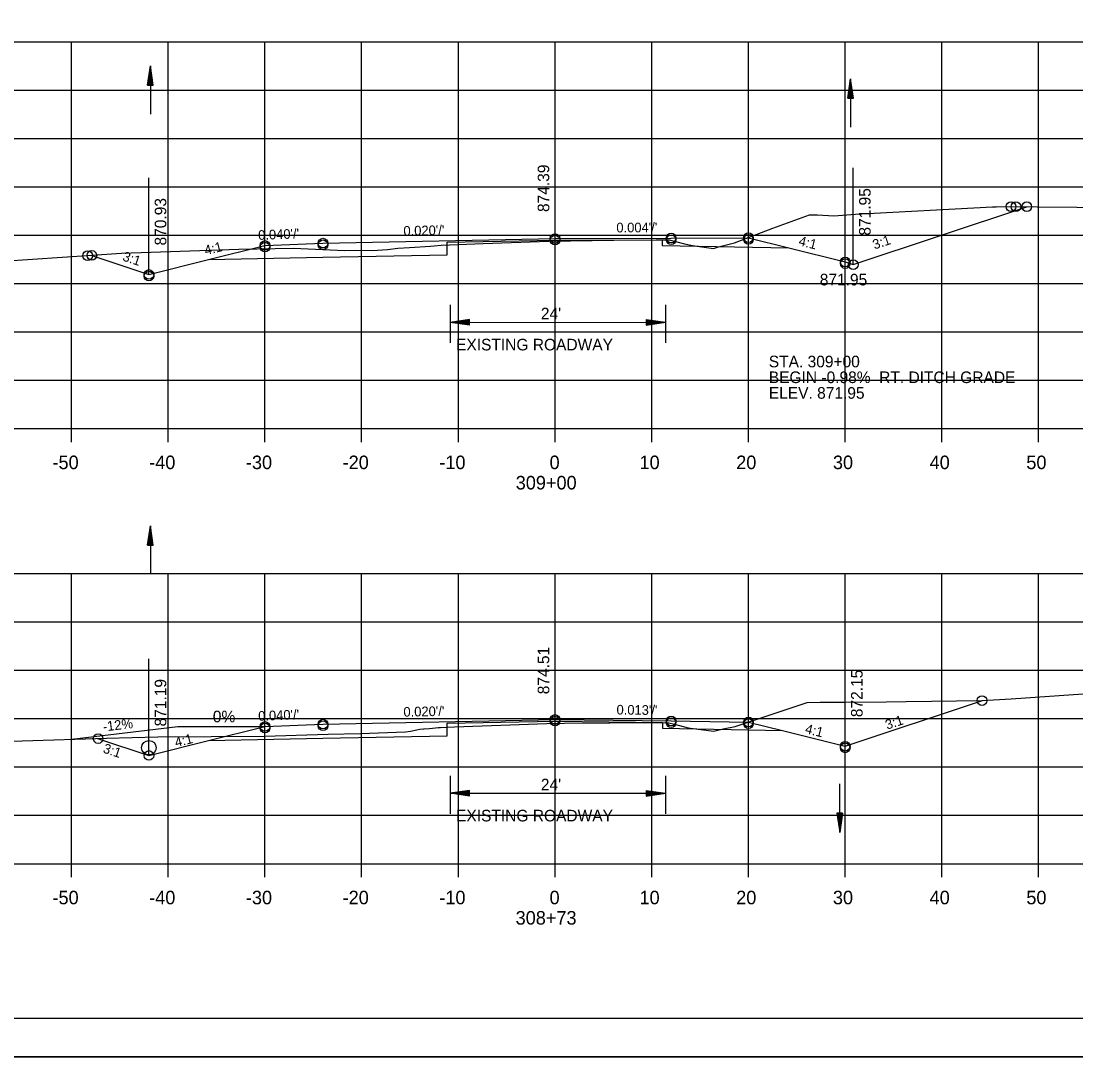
# Model space of a CAD drawing. Extents: x 1486524 to 1499135, y 326561 to 337924.
# Drawn here: x 1488927.7 to 1489036.7, y 334699.3 to 334806.5 of the extents above; entities that cross this region are included whole.
import ezdxf

# ---------------------------------------------------------------- set-up
doc = ezdxf.new("R2010")
doc.units = 0
for name, color, linetype in [('E_Const Align', 7, 'Continuous'), ('E_Const Align Station', 7, 'Continuous'), ('E_Ownership Information', 7, 'Continuous'), ('E_Property Line', 7, 'Continuous'), ('E_Proposed ROW and Easements', 7, 'Continuous'), ('E_Proposed ROW Fig Annot', 7, 'Continuous'), ('E_Quarter Calls', 7, 'Continuous'), ('E_Station Offset', 7, 'Continuous'), ('E_Survey Point', 7, 'Continuous'), ('E_Title Sheet', 7, 'Continuous'), ('E_Tract Number', 7, 'Continuous'), ('R_Water Annot', 7, 'Continuous'), ('R_Xsect Elev', 7, 'Continuous'), ('R_Xsect Slope', 7, 'Continuous')]:
    doc.layers.add(name, color=color, linetype=linetype)

msp = doc.modelspace()

# ---------------------------------------------------------------- linework, layer by layer
at = {"layer": 'E_Const Align'}
for p, q in [((1488842.89, 334764.33), (1489122.89, 334764.33)), ((1488932.89, 334762.93), (1488932.89, 334764.33)), ((1488942.89, 334762.93), (1488942.89, 334764.33)), ((1488952.89, 334762.93), (1488952.89, 334764.33)), ((1488962.89, 334762.93), (1488962.89, 334764.33)), ((1488972.89, 334762.93), (1488972.89, 334764.33)), ((1488982.89, 334762.93), (1488982.89, 334764.33)), ((1488992.89, 334762.93), (1488992.89, 334764.33)), ((1489002.89, 334762.93), (1489002.89, 334764.33)), ((1489012.89, 334762.93), (1489012.89, 334764.33)), ((1489022.89, 334762.93), (1489022.89, 334764.33)), ((1489032.89, 334762.93), (1489032.89, 334764.33)), ((1488842.89, 334719.33), (1489122.89, 334719.33)), ((1488932.89, 334717.93), (1488932.89, 334719.33)), ((1488942.89, 334717.93), (1488942.89, 334719.33)), ((1488952.89, 334717.93), (1488952.89, 334719.33)), ((1488962.89, 334717.93), (1488962.89, 334719.33)), ((1488972.89, 334717.93), (1488972.89, 334719.33)), ((1488982.89, 334717.93), (1488982.89, 334719.33)), ((1488992.89, 334717.93), (1488992.89, 334719.33)), ((1489002.89, 334717.93), (1489002.89, 334719.33)), ((1489012.89, 334717.93), (1489012.89, 334719.33)), ((1489022.89, 334717.93), (1489022.89, 334719.33)), ((1489032.89, 334717.93), (1489032.89, 334719.33))]:
    msp.add_line(p, q, dxfattribs=at)
at = {"layer": 'E_Ownership Information'}
for p, q in [((1488842.89, 334804.33), (1489122.89, 334804.33)), ((1488932.89, 334764.33), (1488932.89, 334804.33)), ((1488942.89, 334764.33), (1488942.89, 334804.33)), ((1488952.89, 334764.33), (1488952.89, 334804.33)), ((1488962.89, 334764.33), (1488962.89, 334804.33)), ((1488972.89, 334764.33), (1488972.89, 334804.33)), ((1488982.89, 334764.33), (1488982.89, 334804.33)), ((1488992.89, 334764.33), (1488992.89, 334804.33)), ((1489002.89, 334764.33), (1489002.89, 334804.33)), ((1489012.89, 334764.33), (1489012.89, 334804.33)), ((1489022.89, 334764.33), (1489022.89, 334804.33)), ((1489032.89, 334764.33), (1489032.89, 334804.33)), ((1488842.89, 334799.33), (1489122.89, 334799.33)), ((1488842.89, 334794.33), (1489122.89, 334794.33)), ((1488842.89, 334789.33), (1489122.89, 334789.33)), ((1488842.89, 334784.33), (1489122.89, 334784.33)), ((1488843.82, 334779.33), (1489123.82, 334779.33)), ((1488842.89, 334774.33), (1489122.89, 334774.33)), ((1488842.89, 334769.33), (1489122.89, 334769.33)), ((1488842.89, 334764.33), (1489122.89, 334764.33)), ((1488842.89, 334749.33), (1489122.89, 334749.33)), ((1488932.89, 334719.33), (1488932.89, 334749.33)), ((1488942.89, 334719.33), (1488942.89, 334749.33)), ((1488952.89, 334719.33), (1488952.89, 334749.33)), ((1488962.89, 334719.33), (1488962.89, 334749.33)), ((1488972.89, 334719.33), (1488972.89, 334749.33)), ((1488982.89, 334719.33), (1488982.89, 334749.33)), ((1488992.89, 334719.33), (1488992.89, 334749.33)), ((1489002.89, 334719.33), (1489002.89, 334749.33)), ((1489012.89, 334719.33), (1489012.89, 334749.33)), ((1489022.89, 334719.33), (1489022.89, 334749.33)), ((1489032.89, 334719.33), (1489032.89, 334749.33)), ((1488842.89, 334744.33), (1489122.89, 334744.33)), ((1488842.89, 334739.33), (1489122.89, 334739.33)), ((1488842.89, 334734.33), (1489122.89, 334734.33)), ((1488842.89, 334729.33), (1489122.89, 334729.33)), ((1488842.89, 334724.33), (1489122.89, 334724.33)), ((1488842.89, 334719.33), (1489122.89, 334719.33))]:
    msp.add_line(p, q, dxfattribs=at)
at = {"layer": 'E_Property Line'}
msp.add_line((1489141.07, 334703.33), (1488824.89, 334703.33), dxfattribs=at)
at = {"layer": 'E_Proposed ROW and Easements'}
for p, q in [((1488972.03, 334777.13), (1488972.03, 334773.2)), ((1488994.31, 334777.13), (1488994.31, 334773.2)), ((1488974.03, 334775.62), (1488972.03, 334775.31)), ((1488974.03, 334775.02), (1488972.03, 334775.31)), ((1488974.03, 334775.57), (1488972.37, 334775.31)), ((1488974.03, 334775.07), (1488972.37, 334775.31)), ((1488974.03, 334775.51), (1488972.71, 334775.31)), ((1488974.03, 334775.12), (1488972.71, 334775.31)), ((1488974.03, 334775.46), (1488973.04, 334775.31)), ((1488974.03, 334775.17), (1488973.04, 334775.31)), ((1488974.03, 334775.41), (1488973.38, 334775.31)), ((1488974.03, 334775.22), (1488973.38, 334775.31)), ((1488974.03, 334775.36), (1488973.72, 334775.31)), ((1488974.03, 334775.27), (1488973.72, 334775.31)), ((1488974.03, 334775.02), (1488974.03, 334775.62)), ((1488992.31, 334775.62), (1488994.31, 334775.32)), ((1488992.31, 334775.62), (1488992.31, 334775.02)), ((1488992.31, 334775.57), (1488993.97, 334775.32)), ((1488992.31, 334775.52), (1488993.63, 334775.32)), ((1488992.31, 334775.47), (1488993.3, 334775.32)), ((1488992.31, 334775.42), (1488992.96, 334775.32)), ((1488992.31, 334775.37), (1488992.62, 334775.32)), ((1488992.31, 334775.02), (1488994.31, 334775.32)), ((1488992.31, 334775.22), (1488992.96, 334775.32)), ((1488992.31, 334775.12), (1488993.63, 334775.32)), ((1488992.31, 334775.07), (1488993.97, 334775.32)), ((1488992.31, 334775.17), (1488993.3, 334775.32)), ((1488992.31, 334775.27), (1488992.62, 334775.32)), ((1488972.03, 334728.42), (1488972.03, 334724.5)), ((1488994.31, 334728.42), (1488994.31, 334724.5)), ((1488974.03, 334726.91), (1488972.03, 334726.61)), ((1488974.03, 334726.86), (1488972.37, 334726.61)), ((1488974.03, 334726.31), (1488974.03, 334726.91)), ((1488992.31, 334726.91), (1488994.31, 334726.61)), ((1488992.31, 334726.91), (1488992.31, 334726.31)), ((1488992.31, 334726.86), (1488993.97, 334726.61)), ((1488974.03, 334726.31), (1488972.03, 334726.61)), ((1488974.03, 334726.36), (1488972.37, 334726.61)), ((1488974.03, 334726.81), (1488972.71, 334726.61)), ((1488974.03, 334726.41), (1488972.71, 334726.61)), ((1488974.03, 334726.76), (1488973.04, 334726.61)), ((1488974.03, 334726.46), (1488973.04, 334726.61)), ((1488974.03, 334726.7), (1488973.38, 334726.61)), ((1488974.03, 334726.51), (1488973.38, 334726.61)), ((1488974.03, 334726.65), (1488973.72, 334726.61)), ((1488974.03, 334726.56), (1488973.72, 334726.61)), ((1488992.31, 334726.81), (1488993.63, 334726.61)), ((1488992.31, 334726.76), (1488993.3, 334726.61)), ((1488992.31, 334726.71), (1488992.96, 334726.61)), ((1488992.31, 334726.66), (1488992.62, 334726.61)), ((1488992.31, 334726.31), (1488994.31, 334726.61)), ((1488992.31, 334726.51), (1488992.96, 334726.61)), ((1488992.31, 334726.41), (1488993.63, 334726.61)), ((1488992.31, 334726.36), (1488993.97, 334726.61)), ((1488992.31, 334726.46), (1488993.3, 334726.61)), ((1488992.31, 334726.56), (1488992.62, 334726.61))]:
    msp.add_line(p, q, dxfattribs=at)
at = {"layer": 'E_Proposed ROW Fig Annot'}
for p, q in [((1488940.74, 334799.85), (1488941.04, 334801.85)), ((1488940.79, 334799.85), (1488941.04, 334801.51)), ((1488940.84, 334799.85), (1488941.04, 334801.17)), ((1488941.34, 334799.85), (1488941.04, 334801.85)), ((1488941.29, 334799.85), (1488941.04, 334801.51)), ((1488941.24, 334799.85), (1488941.04, 334801.17)), ((1488940.89, 334799.85), (1488941.04, 334800.84)), ((1488940.94, 334799.85), (1488941.04, 334800.5)), ((1488940.99, 334799.85), (1488941.04, 334800.16)), ((1488941.19, 334799.85), (1488941.04, 334800.84)), ((1488941.14, 334799.85), (1488941.04, 334800.5)), ((1488941.09, 334799.85), (1488941.04, 334800.16)), ((1489013.15, 334798.49), (1489013.45, 334800.49)), ((1489013.2, 334798.49), (1489013.45, 334800.16)), ((1489013.75, 334798.49), (1489013.45, 334800.49)), ((1489013.7, 334798.49), (1489013.45, 334800.16)), ((1488940.74, 334799.85), (1488941.34, 334799.85)), ((1489013.25, 334798.49), (1489013.45, 334799.82)), ((1489013.3, 334798.49), (1489013.45, 334799.48)), ((1489013.36, 334798.49), (1489013.45, 334799.14)), ((1489013.41, 334798.49), (1489013.45, 334798.81)), ((1489013.65, 334798.49), (1489013.45, 334799.82)), ((1489013.6, 334798.49), (1489013.45, 334799.48)), ((1489013.55, 334798.49), (1489013.45, 334799.14)), ((1489013.5, 334798.49), (1489013.45, 334798.81)), ((1489013.15, 334798.49), (1489013.75, 334798.49)), ((1488972.03, 334775.31), (1488994.31, 334775.32)), ((1488940.74, 334752.27), (1488941.04, 334754.27)), ((1488941.34, 334752.27), (1488941.04, 334754.27)), ((1488940.79, 334752.27), (1488941.04, 334753.93)), ((1488940.84, 334752.27), (1488941.04, 334753.59)), ((1488940.89, 334752.27), (1488941.04, 334753.25)), ((1488941.29, 334752.27), (1488941.04, 334753.93)), ((1488941.24, 334752.27), (1488941.04, 334753.59)), ((1488941.19, 334752.27), (1488941.04, 334753.25)), ((1488940.74, 334752.27), (1488941.34, 334752.27)), ((1488940.94, 334752.27), (1488941.04, 334752.92)), ((1488940.99, 334752.27), (1488941.04, 334752.58)), ((1488941.14, 334752.27), (1488941.04, 334752.92)), ((1488941.09, 334752.27), (1488941.04, 334752.58)), ((1488972.03, 334726.61), (1488994.31, 334726.61)), ((1489012.02, 334724.57), (1489012.32, 334722.57)), ((1489012.62, 334724.57), (1489012.02, 334724.57)), ((1489012.07, 334724.57), (1489012.32, 334722.9)), ((1489012.12, 334724.57), (1489012.32, 334723.25)), ((1489012.17, 334724.57), (1489012.32, 334723.58)), ((1489012.22, 334724.57), (1489012.32, 334723.92)), ((1489012.27, 334724.57), (1489012.32, 334724.25)), ((1489012.62, 334724.57), (1489012.32, 334722.57)), ((1489012.41, 334724.57), (1489012.32, 334723.92)), ((1489012.52, 334724.57), (1489012.32, 334723.25)), ((1489012.57, 334724.57), (1489012.32, 334722.9)), ((1489012.47, 334724.57), (1489012.32, 334723.58)), ((1489012.36, 334724.57), (1489012.32, 334724.25))]:
    msp.add_line(p, q, dxfattribs=at)
at = {"layer": 'E_Quarter Calls'}
msp.add_line((1488812.48, 334699.35), (1489145.82, 334699.35), dxfattribs=at)
for points in [[(1488812.48, 334912.69), (1489145.82, 334912.69), (1489145.82, 334699.35), (1488812.48, 334699.35)], [(1489058.81, 334908.79), (1489058.81, 334898.91), (1489094.54, 334898.91), (1489094.54, 334895.99), (1489117.74, 334895.99), (1489117.74, 334871.66), (1489141.07, 334871.66), (1489141.07, 334703.33), (1488824.89, 334703.33), (1488824.89, 334908.79)]]:
    msp.add_lwpolyline(points, close=True, dxfattribs=at)
for centre in [(1489030.04, 334787.28), (1489030.54, 334787.27), (1489031.67, 334787.27), (1488952.89, 334783.26), (1488952.89, 334783.26), (1488952.89, 334783.09), (1488958.89, 334783.5), (1488958.89, 334783.5), (1488958.89, 334783.33), (1488982.89, 334783.98), (1488982.89, 334783.98), (1488982.89, 334783.81), (1488994.89, 334784.03), (1488994.89, 334784.03), (1488994.89, 334783.86), (1489002.89, 334784.06), (1489002.89, 334784.06), (1489002.89, 334783.89), (1488934.56, 334782.2), (1488934.99, 334782.23), (1488934.99, 334782.23), (1489012.89, 334781.56), (1489012.89, 334781.56), (1489012.89, 334781.39), (1489013.72, 334781.28), (1488940.89, 334780.26), (1488940.89, 334780.26), (1488940.89, 334780.09), (1489027.04, 334736.2), (1489027.04, 334736.2), (1488982.89, 334734.24), (1488982.89, 334734.24), (1488982.89, 334734.07), (1488994.89, 334734.09), (1488994.89, 334734.09), (1489002.89, 334733.98), (1489002.89, 334733.98), (1488952.89, 334733.52), (1488952.89, 334733.52), (1488952.89, 334733.35), (1488958.89, 334733.76), (1488958.89, 334733.76), (1488958.89, 334733.59), (1488994.89, 334733.92), (1489002.89, 334733.81), (1488935.64, 334732.27), (1488935.64, 334732.27), (1489012.89, 334731.48), (1489012.89, 334731.48), (1489012.89, 334731.31), (1488940.89, 334730.52), (1488940.89, 334730.52)]:
    msp.add_circle(centre, 0.5, dxfattribs=at)
at = {"layer": 'E_Station Offset'}
for p, q in [((1488932.93, 334732.21), (1488943.89, 334733.52)), ((1488943.89, 334733.52), (1488952.89, 334733.52))]:
    msp.add_line(p, q, dxfattribs=at)
msp.add_circle((1488940.89, 334731.32), 0.75, dxfattribs=at)
at = {"layer": 'E_Survey Point'}
for points in [[(1488947.06, 334781.8), (1488958.89, 334782.04), (1488971.72, 334782.3), (1488971.72, 334783.59), (1488982.89, 334783.81), (1488993.97, 334783.86), (1488993.98, 334783.27), (1489007.07, 334783.01)], [(1488947.06, 334732.06), (1488958.89, 334732.3), (1488971.72, 334732.56), (1488971.72, 334733.85), (1488982.89, 334734.07), (1488993.99, 334733.93), (1488994, 334733.35), (1489006.42, 334733.1)]]:
    msp.add_lwpolyline(points, dxfattribs=at)
at = {"layer": 'E_Title Sheet'}
for points in [[(1488934.99, 334782.23), (1488940.89, 334780.26), (1488947.06, 334781.8), (1488952.89, 334783.26), (1488958.89, 334783.5), (1488982.89, 334783.98), (1488994.89, 334784.03), (1489002.89, 334784.06), (1489007.07, 334783.01), (1489012.89, 334781.56), (1489013.72, 334781.28), (1489031.67, 334787.27)], [(1488935.57, 334732.29), (1488940.89, 334730.52), (1488947.06, 334732.06), (1488952.89, 334733.52), (1488958.89, 334733.76), (1488982.89, 334734.24), (1488994.89, 334734.09), (1489002.89, 334733.98), (1489006.42, 334733.1), (1489012.89, 334731.48), (1489027.1, 334736.22)]]:
    msp.add_lwpolyline(points, dxfattribs=at)
at = {"layer": 'E_Tract Number'}
for points in [[(1488925.78, 334781.65), (1488938.04, 334782.47), (1488950.18, 334782.88), (1488955.85, 334782.99), (1488957.36, 334782.9), (1488961.14, 334782.74), (1488962.28, 334782.76), (1488964.01, 334782.75), (1488965.56, 334782.86), (1488966.64, 334782.98), (1488967.84, 334783.06), (1488970.02, 334783.2), (1488970.38, 334783.23), (1488971.1, 334783.29), (1488975.45, 334783.45), (1488982.23, 334783.71), (1488988.97, 334783.81), (1488993.35, 334783.85), (1488993.87, 334783.84), (1488994.68, 334783.83), (1488996.29, 334783.44), (1488997.11, 334783.27), (1488997.57, 334783.2), (1488999.26, 334782.96), (1488999.8, 334783.11), (1489001.44, 334783.53), (1489005.42, 334785.04), (1489009.21, 334786.44), (1489010.01, 334786.42), (1489011.73, 334786.33), (1489013.95, 334786.51), (1489028.12, 334787.26), (1489028.51, 334787.27), (1489028.68, 334787.28), (1489040.92, 334787.18)], [(1488924.36, 334731.94), (1488927.77, 334732.05), (1488936.51, 334732.32), (1488941.8, 334732.46), (1488952.86, 334732.53), (1488959.43, 334732.71), (1488962.77, 334732.8), (1488967.43, 334732.95), (1488967.94, 334733.03), (1488968.59, 334733.16), (1488968.92, 334733.25), (1488969.27, 334733.27), (1488969.37, 334733.27), (1488969.92, 334733.31), (1488970.84, 334733.4), (1488971.04, 334733.42), (1488972.48, 334733.48), (1488982.05, 334733.84), (1488983.82, 334733.85), (1488993.31, 334733.93), (1488994.39, 334733.9), (1488994.67, 334733.9), (1488995.25, 334733.76), (1488996.64, 334733.39), (1488997.67, 334733.25), (1488999.3, 334733.04), (1489000.28, 334733.26), (1489001.51, 334733.53), (1489007.92, 334735.66), (1489008.94, 334736.01), (1489010.31, 334736.03), (1489012.38, 334736.03), (1489012.84, 334736.02), (1489017.11, 334736.07), (1489019.2, 334736.11), (1489027.01, 334736.22), (1489030.04, 334736.37), (1489054.86, 334738.09)]]:
    msp.add_lwpolyline(points, dxfattribs=at)
at = {"layer": 'R_Water Annot'}
for p, q in [((1488941.04, 334801.85), (1488941.04, 334796.85)), ((1489013.45, 334800.49), (1489013.45, 334795.49)), ((1488941.04, 334754.27), (1488941.04, 334749.27)), ((1489012.32, 334722.57), (1489012.32, 334727.57))]:
    msp.add_line(p, q, dxfattribs=at)
at = {"layer": 'R_Xsect Elev'}
for p, q in [((1488982.89, 334783.72), (1488982.89, 334793.72)), ((1489013.72, 334781.28), (1489013.72, 334791.28)), ((1488940.89, 334780.26), (1488940.89, 334790.26)), ((1488982.89, 334733.85), (1488982.89, 334743.85)), ((1489012.89, 334731.48), (1489012.89, 334741.48)), ((1488940.89, 334730.52), (1488940.89, 334740.52))]:
    msp.add_line(p, q, dxfattribs=at)

# ---------------------------------------------------------------- texts
at = {"layer": 'E_Const Align Station'}
for s, p in [('-50', (1488930.92, 334760.13)), ('-40', (1488940.92, 334760.13)), ('-30', (1488950.92, 334760.13)), ('-20', (1488960.92, 334760.13)), ('-10', (1488970.92, 334760.13)), ('0', (1488982.32, 334760.13)), ('10', (1488991.62, 334760.13)), ('20', (1489001.62, 334760.13)), ('30', (1489011.62, 334760.13)), ('40', (1489021.62, 334760.13)), ('50', (1489031.62, 334760.13)), ('309+00', (1488978.82, 334758.03)), ('-50', (1488930.92, 334715.13)), ('-40', (1488940.92, 334715.13)), ('-30', (1488950.92, 334715.13)), ('-20', (1488960.92, 334715.13)), ('-10', (1488970.92, 334715.13)), ('0', (1488982.32, 334715.13)), ('10', (1488991.62, 334715.13)), ('20', (1489001.62, 334715.13)), ('30', (1489011.62, 334715.13)), ('40', (1489021.62, 334715.13)), ('50', (1489031.62, 334715.13)), ('308+73', (1488978.81, 334713.03))]:
    msp.add_text(s, height=1.4, dxfattribs=at).set_placement(p)
at = {"layer": 'E_Proposed ROW Fig Annot'}
for s, p in [("24'", (1488981.42, 334775.62)), ('EXISTING ROADWAY', (1488972.65, 334772.41)), ('STA. 309+00 ', (1489004.99, 334770.66)), ('BEGIN -0.98%  RT. DITCH GRADE', (1489004.99, 334769.03)), ('ELEV. 871.95', (1489004.99, 334767.41)), ("24'", (1488981.42, 334726.91)), ('EXISTING ROADWAY', (1488972.65, 334723.7))]:
    msp.add_text(s, height=1.2, dxfattribs=at).set_placement(p)
at = {"layer": 'E_Station Offset'}
msp.add_text('0%', height=1.2, dxfattribs=at).set_placement((1488947.5, 334733.95))
msp.add_text('-12%', height=1, rotation=6.84, dxfattribs=at).set_placement((1488936.19, 334732.99))
at = {"layer": 'R_Xsect Elev'}
for s, p in [('874.39', (1488982.29, 334786.72)), ('871.95', (1489015.52, 334784.28)), ('870.93', (1488942.69, 334783.26)), ('874.51', (1488982.29, 334736.85)), ('872.15', (1489014.69, 334734.48)), ('871.19', (1488942.69, 334733.52))]:
    msp.add_text(s, height=1.2, rotation=90, dxfattribs=at).set_placement(p)
msp.add_text('871.95', height=1.2, dxfattribs=at).set_placement((1489010.26, 334779.13))
at = {"layer": 'R_Xsect Slope'}
for s, rotation, p in [("0.040'/'", 2.2906, (1488952.21, 334783.83)), ("0.020'/'", 1.1458, (1488967.22, 334784.27)), ("0.004'/'", 0.2245, (1488989.23, 334784.61)), ('4:1', 14.0362, (1488946.76, 334782.25)), ('4:1', 345.9638, (1489008.01, 334783.29)), ('3:1', 18.4349, (1489015.92, 334782.84)), ('3:1', 341.5651, (1488938.09, 334781.72)), ("0.020'/'", 1.1458, (1488967.22, 334734.53)), ("0.013'/'", 359.2594, (1488989.24, 334734.76)), ("0.040'/'", 2.2906, (1488952.21, 334734.1)), ('3:1', 18.4349, (1489017.23, 334733.18)), ('4:1', 345.9638, (1489008.68, 334732.84)), ('4:1', 14.0362, (1488943.7, 334731.37)), ('3:1', 341.5651, (1488936.07, 334730.84))]:
    msp.add_text(s, height=1, rotation=rotation, dxfattribs=at).set_placement(p)

doc.saveas('drawing.dxf')
